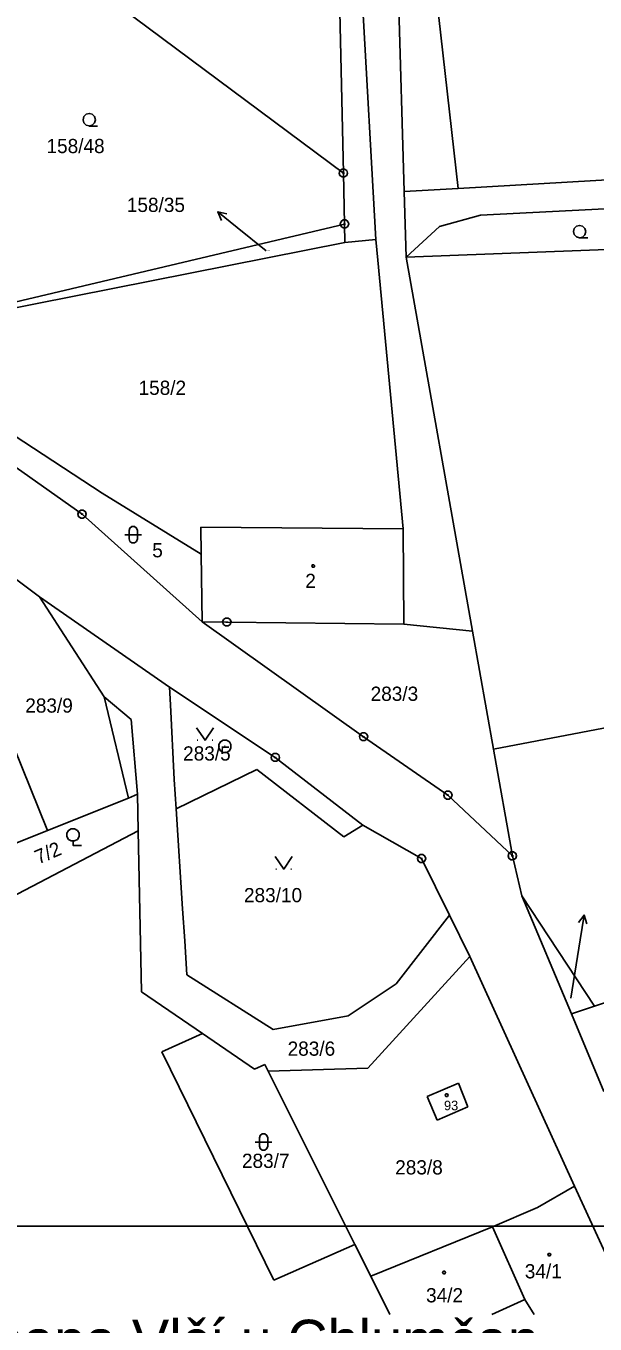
# Model space of a CAD drawing. Extents: x -779723 to -777378, y -1011169 to -1009297.
# Drawn here: x -779263.9 to -779195.8, y -1010279.6 to -1010124.4 of the extents above; entities that cross this region are included whole.
import ezdxf

# ---------------------------------------------------------------- set-up
doc = ezdxf.new("R2010")
doc.units = 0
for name, color, linetype in [('Default', 7, 'Continuous'), ('KN_HRANICE', 7, 'Continuous'), ('KN_KULTURY', 7, 'Continuous'), ('KN_PARCELY', 7, 'Continuous'), ('KN_SLUCKY', 7, 'Continuous'), ('LEGENDA', 7, 'Continuous')]:
    doc.layers.add(name, color=color, linetype=linetype)

# ---------------------------------------------------------------- blocks, each defined once
blk = doc.blocks.new('101')
at = {"layer": 'Default'}
blk.add_line((-0.05, 0), (0.05, 0), dxfattribs=at)
blk.add_lwpolyline([(0.19, 0.72), (0.53, 0.53), (0.72, 0.19), (0.72, -0.2), (0.53, -0.54), (0.19, -0.73), (-0.2, -0.73), (-0.54, -0.54), (-0.73, -0.2), (-0.73, 0.19), (-0.54, 0.53), (-0.2, 0.72), (0.19, 0.72)], dxfattribs=at)
blk = doc.blocks.new('304')
at = {"layer": 'Default'}
blk.add_lwpolyline([(0, 0), (-0.38, 0.1), (-0.65, 0.37), (-0.75, 0.74), (-0.65, 1.11), (-0.38, 1.38), (-0.01, 1.48), (0.36, 1.38), (0.63, 1.11), (0.73, 0.73), (0.63, 0.35), (0.36, 0.08), (-0.02, -0.02), (0.98, -0.02)], dxfattribs=at)
blk = doc.blocks.new('305')
at = {"layer": 'Default'}
blk.add_lwpolyline([(0, 0.53), (-0.19, 0.53), (-0.53, 0.72), (-0.72, 1.06), (-0.72, 1.45), (-0.53, 1.79), (-0.19, 1.98), (0.2, 1.98), (0.54, 1.79), (0.73, 1.45), (0.73, 1.06), (0.54, 0.72), (0.2, 0.53), (0.01, 0.53), (0.01, 0), (1.01, 0)], dxfattribs=at)
blk = doc.blocks.new('314')
at = {"layer": 'Default'}
for p, q in [((-0.95, 0), (-0.85, 0)), ((0.85, 0), (0.95, 0))]:
    blk.add_line(p, q, dxfattribs=at)
blk.add_lwpolyline([(-1, 1.5), (0, 0), (1, 1.5)], dxfattribs=at)
blk = doc.blocks.new('316')
at = {"layer": 'Default'}
for points in [[(-0.5, 1.5), (-0.4, 1.79), (-0.15, 1.97), (0.16, 1.97), (0.41, 1.79), (0.51, 1.5), (0.51, 0.5), (0.41, 0.21), (0.16, 0.03), (-0.15, 0.03), (-0.4, 0.21), (-0.5, 0.5), (-0.5, 1.5)], [(-1, 1), (0.27, 1), (1, 1)]]:
    blk.add_lwpolyline(points, dxfattribs=at)
blk = doc.blocks.new('NAHRADNI_SYMBOL')
at = {"layer": 'Default'}
blk.add_lwpolyline([(0.09, 0.15), (0.18, 0), (0.09, -0.15), (-0.09, -0.15), (-0.18, 0), (-0.09, 0.15), (0.09, 0.15)], dxfattribs=at)
blk = doc.blocks.new('10292')
at = {"layer": 'Default'}
blk.add_line((0, 3), (0, 0), dxfattribs=at)
blk.add_lwpolyline([(-0.5, 2), (0, 3), (0.5, 2)], dxfattribs=at)
blk = doc.blocks.new('105')
at = {"layer": 'Default'}
blk.add_line((-0.12, 0), (0.12, 0), dxfattribs=at)
blk.add_lwpolyline([(0.15, 0.48), (0.4, 0.3), (0.5, 0.01), (0.4, -0.28), (0.15, -0.46), (-0.16, -0.46), (-0.41, -0.28), (-0.51, 0.01), (-0.41, 0.3), (-0.16, 0.48), (0.15, 0.48)], dxfattribs=at)
blk = doc.blocks.new('402')
at = {"layer": 'Default'}
blk.add_lwpolyline([(0.09, 0.15), (0.18, 0), (0.09, -0.15), (-0.09, -0.15), (-0.18, 0), (-0.09, 0.15), (0.09, 0.15)], dxfattribs=at)

msp = doc.modelspace()

# ---------------------------------------------------------------- linework, layer by layer
at = {"layer": 'KN_HRANICE'}
for p, q in [((-779218.82, -1010085.26), (-779212.16, -1010143.8)), ((-779218.61, -1010144.17), (-779219.75, -1010106.05)), ((-779224.22, -1010110.43), (-779222.02, -1010149.91)), ((-779225.9, -1010141.96), (-779262.32, -1010114.82)), ((-779225.9, -1010141.96), (-779226.51, -1010114.99)), ((-779134.25, -1010139.27), (-779212.16, -1010143.8)), ((-779225.76, -1010148.05), (-779225.9, -1010141.96)), ((-779212.16, -1010143.8), (-779218.61, -1010144.17)), ((-779218.39, -1010152.01), (-779218.61, -1010144.17)), ((-779168.53, -1010144.84), (-779209.48, -1010147.01)), ((-779214.4, -1010148.33), (-779209.48, -1010147.01)), ((-779225.76, -1010148.05), (-779265.87, -1010157.54)), ((-779225.76, -1010148.05), (-779225.71, -1010150.28)), ((-779218.39, -1010152.01), (-779214.4, -1010148.33)), ((-779283.36, -1010161.68), (-779225.71, -1010150.28)), ((-779225.71, -1010150.28), (-779222.02, -1010149.91)), ((-779222.02, -1010149.91), (-779221.79, -1010152.36)), ((-779168.07, -1010150.12), (-779218.39, -1010152.01)), ((-779221.79, -1010152.36), (-779218.76, -1010184.53)), ((-779210.46, -1010196.74), (-779218.39, -1010152.01)), ((-779265.26, -1010173.35), (-779254.75, -1010180.24)), ((-779270.09, -1010173.63), (-779257.16, -1010182.76)), ((-779254.75, -1010180.24), (-779242.9, -1010187.56)), ((-779257.16, -1010182.76), (-779242.79, -1010195.65)), ((-779242.94, -1010184.31), (-779218.76, -1010184.53)), ((-779242.9, -1010187.56), (-779242.94, -1010184.31)), ((-779218.76, -1010184.53), (-779218.67, -1010195.92)), ((-779242.79, -1010195.65), (-779242.9, -1010187.56)), ((-779268.33, -1010188.11), (-779262.24, -1010192.63)), ((-779273.57, -1010190.29), (-779261.29, -1010220.59)), ((-779262.24, -1010192.63), (-779254.52, -1010204.61)), ((-779246.71, -1010203.46), (-779262.24, -1010192.63)), ((-779242.79, -1010195.65), (-779223.48, -1010209.38)), ((-779239.83, -1010195.66), (-779242.79, -1010195.65)), ((-779218.67, -1010195.92), (-779239.83, -1010195.66)), ((-779218.67, -1010195.92), (-779210.46, -1010196.74)), ((-779207.96, -1010210.85), (-779210.46, -1010196.74)), ((-779254.52, -1010204.61), (-779251.62, -1010216.72)), ((-779246.59, -1010205.57), (-779246.71, -1010203.46)), ((-779246.71, -1010203.46), (-779234.04, -1010211.86)), ((-779207.96, -1010210.85), (-779167.91, -1010203.3)), ((-779246.59, -1010205.57), (-779246.15, -1010214.51)), ((-779223.48, -1010209.38), (-779213.39, -1010216.37)), ((-779205.69, -1010223.63), (-779207.96, -1010210.85)), ((-779234.04, -1010211.86), (-779223.57, -1010219.94)), ((-779245.92, -1010218.02), (-779236.27, -1010213.3)), ((-779225.85, -1010221.36), (-779236.27, -1010213.3)), ((-779246.15, -1010214.51), (-779245.92, -1010218.02)), ((-779251.62, -1010216.72), (-779261.29, -1010220.59)), ((-779251.62, -1010216.72), (-779250.54, -1010216.27)), ((-779250.45, -1010220.64), (-779250.54, -1010216.27)), ((-779213.39, -1010216.37), (-779205.69, -1010223.63)), ((-779245.92, -1010218.02), (-779245.13, -1010229.97)), ((-779225.85, -1010221.36), (-779223.57, -1010219.94)), ((-779223.57, -1010219.94), (-779216.54, -1010223.96)), ((-779261.29, -1010220.59), (-779273.03, -1010225.28)), ((-779250.45, -1010220.64), (-779267.64, -1010229.61)), ((-779250.04, -1010239.9), (-779250.45, -1010220.64)), ((-779216.54, -1010223.96), (-779213.22, -1010230.72)), ((-779205.69, -1010223.63), (-779204.56, -1010228.41)), ((-779204.56, -1010228.41), (-779198.63, -1010242.53)), ((-779204.56, -1010228.41), (-779195.85, -1010241.6)), ((-779245.13, -1010229.97), (-779244.88, -1010233.78)), ((-779219.59, -1010238.93), (-779213.22, -1010230.72)), ((-779213.22, -1010230.72), (-779210.79, -1010235.65)), ((-779244.88, -1010233.78), (-779244.61, -1010237.88)), ((-779222.98, -1010249.03), (-779210.79, -1010235.65)), ((-779210.79, -1010235.65), (-779198.24, -1010263.13)), ((-779244.61, -1010237.88), (-779234.3, -1010244.39)), ((-779182.98, -1010237.3), (-779195.85, -1010241.6)), ((-779250.04, -1010239.9), (-779242.75, -1010244.88)), ((-779225.31, -1010242.76), (-779219.59, -1010238.93)), ((-779195.85, -1010241.6), (-779198.63, -1010242.53)), ((-779234.3, -1010244.39), (-779225.31, -1010242.76)), ((-779198.63, -1010242.53), (-779194.73, -1010251.82)), ((-779247.62, -1010247.08), (-779242.75, -1010244.88)), ((-779242.75, -1010244.88), (-779236.53, -1010249.13)), ((-779247.62, -1010247.08), (-779234.22, -1010274.39)), ((-779236.53, -1010249.13), (-779235.31, -1010248.59)), ((-779235.31, -1010248.59), (-779234.91, -1010249.39)), ((-779234.91, -1010249.39), (-779222.98, -1010249.03)), ((-779234.91, -1010249.39), (-779224.53, -1010270.12)), ((-779215.86, -1010252.41), (-779212.13, -1010250.84)), ((-779212.13, -1010250.84), (-779211.01, -1010253.67)), ((-779214.7, -1010255.23), (-779215.86, -1010252.41)), ((-779211.01, -1010253.67), (-779214.7, -1010255.23)), ((-779202.67, -1010265.7), (-779198.24, -1010263.13)), ((-779198.24, -1010263.13), (-779191.22, -1010278.51)), ((-779208.06, -1010267.99), (-779202.67, -1010265.7)), ((-779208.06, -1010267.99), (-779222.63, -1010273.91)), ((-779208.06, -1010267.99), (-779204.18, -1010276.69)), ((-779234.22, -1010274.39), (-779224.53, -1010270.12)), ((-779224.53, -1010270.12), (-779222.63, -1010273.91)), ((-779222.63, -1010273.91), (-779220.33, -1010278.51)), ((-779204.18, -1010276.69), (-779208.16, -1010278.51)), ((-779204.18, -1010276.69), (-779203.08, -1010278.51))]:
    msp.add_line(p, q, dxfattribs=at)
at = {"layer": 'KN_PARCELY'}
for p, q in [((-779235.13, -1010151.25), (-779238.59, -1010148.48)), ((-779198.7, -1010240.65), (-779197.58, -1010233.67))]:
    msp.add_line(p, q, dxfattribs=at)
at = {"layer": 'KN_SLUCKY'}
for p in [(-779254.52, -1010204.61), (-779250.54, -1010216.27)]:
    msp.add_line(p, (-779251.28, -1010207.31), dxfattribs=at)
at = {"layer": 'LEGENDA'}
msp.add_lwpolyline([(-779530.66, -1010687.91), (-778936.66, -1010687.91), (-778936.66, -1010267.91), (-779530.66, -1010267.91)], close=True, dxfattribs=at)

# ---------------------------------------------------------------- block references
at = {"layer": 'KN_KULTURY'}
for name, p in [('304', (-779256.29, -1010136.31)), ('304', (-779197.64, -1010149.69)), ('316', (-779251.04, -1010186.22)), ('402', (-779229.51, -1010188.95)), ('314', (-779242.45, -1010209.81)), ('305', (-779258.25, -1010222.38)), ('314', (-779233.04, -1010225.22)), ('402', (-779213.55, -1010252.26)), ('316', (-779235.45, -1010258.86)), ('NAHRADNI_SYMBOL', (-779201.27, -1010271.33)), ('402', (-779213.85, -1010273.46))]:
    msp.add_blockref(name, p, dxfattribs=at)
at = {"layer": 'KN_PARCELY'}
for name, p in [('105', (-779225.9, -1010141.96)), ('105', (-779225.76, -1010148.05)), ('105', (-779257.16, -1010182.76)), ('105', (-779239.83, -1010195.66)), ('105', (-779223.48, -1010209.38)), ('101', (-779240.07, -1010210.52)), ('105', (-779234.04, -1010211.86)), ('105', (-779213.39, -1010216.37)), ('105', (-779205.69, -1010223.63)), ('105', (-779216.54, -1010223.96))]:
    msp.add_blockref(name, p, dxfattribs=at)
for p, rotation in [((-779238.59, -1010148.48), 51.33701799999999), ((-779197.58, -1010233.67), -9.120646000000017)]:
    msp.add_blockref('10292', p, dxfattribs=dict(at, rotation=rotation))

# ---------------------------------------------------------------- texts
for s, height, p in [('158/48', 1.7, (-779261.41, -1010139.57)), ('158/35', 1.7, (-779251.8, -1010146.61)), ('158/35', 0.1, (-779235.11, -1010151.25)), ('158/2', 1.7, (-779250.4, -1010168.49)), ('5', 1.7, (-779248.76, -1010187.92)), ('2', 1.7, (-779230.46, -1010191.59)), ('283/3', 1.7, (-779222.64, -1010205.09)), ('283/9', 1.7, (-779263.95, -1010206.5)), ('283/5', 1.7, (-779245.07, -1010212.23)), ('283/10', 1.7, (-779237.79, -1010229.18)), ('283/4', 0.1, (-779198.69, -1010240.65)), ('283/6', 1.7, (-779232.57, -1010247.54)), ('93', 1.14, (-779213.86, -1010254.06)), ('283/7', 1.7, (-779238.03, -1010260.96)), ('283/8', 1.7, (-779219.7, -1010261.74)), ('34/1', 1.7, (-779204.2, -1010274.17)), ('34/2', 1.7, (-779216.01, -1010277.04))]:
    msp.add_text(s, height=height, dxfattribs=at).set_placement(p)
msp.add_text('7/2', height=1.7, rotation=23.262, dxfattribs=at).set_placement((-779262.37, -1010224.67))
at = {"layer": 'LEGENDA'}
msp.add_text('katastrální mapa Vlčí u Chlumčan', height=5, dxfattribs=at).set_placement((-779302.48, -1010284.12))

doc.saveas('drawing.dxf')
